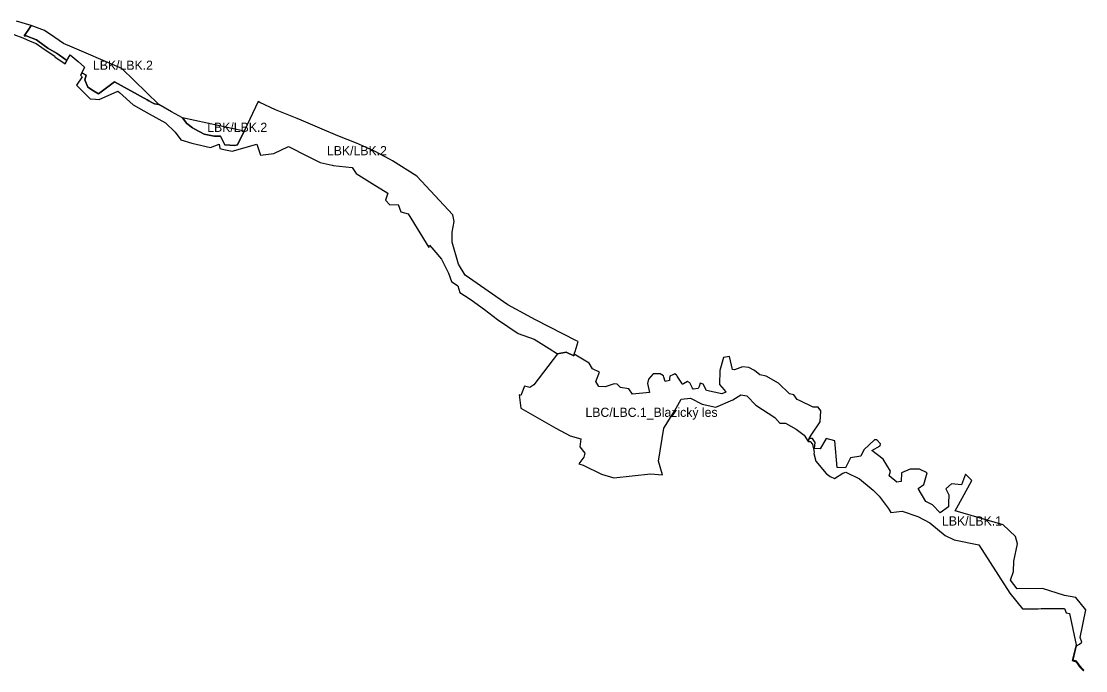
# Model space of a CAD drawing. Extents: x -521980 to -518833, y -1141793 to -1140093.
# Drawn here: x -520226 to -518833, y -1141674 to -1140823 of the extents above; entities that cross this region are included whole.
import ezdxf

# ---------------------------------------------------------------- set-up
doc = ezdxf.new("R2010")
doc.units = 0
for name, color, linetype in [('91270013', 7, 'Continuous'), ('91280013', 7, 'Continuous'), ('91280023', 7, 'Continuous')]:
    doc.layers.add(name, color=color, linetype=linetype)

msp = doc.modelspace()

# ---------------------------------------------------------------- linework, layer by layer
at = {"layer": '91270013'}
msp.add_lwpolyline([(-519524.47, -1141258.63), (-519555.19, -1141299.24), (-519560.68, -1141302.79), (-519567.64, -1141300.94), (-519572.4, -1141313.2), (-519574.58, -1141312.28), (-519572.25, -1141330.06), (-519526.67, -1141356.01), (-519507.9, -1141366.28), (-519493.9, -1141370.24), (-519494.92, -1141380.6), (-519488.36, -1141388.76), (-519489.99, -1141393.96), (-519496.45, -1141402.69), (-519490.7, -1141404.57), (-519466.91, -1141416.21), (-519450.75, -1141420.94), (-519402.53, -1141416.1), (-519386.73, -1141417.35), (-519392.16, -1141399.31), (-519385.2, -1141356.16), (-519371.28, -1141333.68), (-519362.63, -1141317.99), (-519350.02, -1141316.82), (-519334.98, -1141324.76), (-519317.19, -1141328.69), (-519294.89, -1141319.05), (-519284.21, -1141312.41), (-519276.42, -1141313.78), (-519264.89, -1141325.79), (-519239.84, -1141342.13), (-519233.32, -1141349.64), (-519225.95, -1141349.55), (-519211.68, -1141357.48), (-519201.22, -1141365.24), (-519195.98, -1141373.38), (-519194.96, -1141369.43), (-519192.3, -1141365.49), (-519180.48, -1141347.87), (-519179.55, -1141333.52), (-519183.26, -1141328.59), (-519189.49, -1141328.56), (-519206.65, -1141320.44), (-519210.53, -1141318.6), (-519214.82, -1141312.52), (-519220.59, -1141311.22), (-519234.97, -1141297.23), (-519251.16, -1141288.07), (-519259.58, -1141286.33), (-519266.36, -1141280.43), (-519273.89, -1141276.5), (-519282.24, -1141275.71), (-519292.59, -1141279.53), (-519295.1, -1141279.15), (-519299.19, -1141262.23), (-519306.82, -1141263.47), (-519311.83, -1141280.54), (-519312.28, -1141299.01), (-519305.93, -1141305.82), (-519304.74, -1141307.68), (-519303.86, -1141309.05), (-519309.3, -1141311.02), (-519329.18, -1141306.68), (-519333.7, -1141298.67), (-519337.51, -1141297.26), (-519339.07, -1141301.4), (-519340.12, -1141304.19), (-519346.7, -1141305.23), (-519347.55, -1141303.63), (-519351.06, -1141296.96), (-519353.95, -1141294.93), (-519359.18, -1141298.18), (-519360.6, -1141299.07), (-519361.74, -1141297.24), (-519367.51, -1141288.01), (-519368.04, -1141287.17), (-519370.55, -1141284.76), (-519373.33, -1141286.11), (-519377.33, -1141288.06), (-519377.66, -1141291.53), (-519377.88, -1141293.85), (-519383.31, -1141295.11), (-519385.12, -1141289.38), (-519385.69, -1141287.55), (-519389.78, -1141285.13), (-519399.13, -1141285.07), (-519405.2, -1141292.02), (-519406.68, -1141297.5), (-519403.83, -1141309.49), (-519426.16, -1141311.48), (-519430.99, -1141304.77), (-519441.7, -1141302.87), (-519446.22, -1141298.48), (-519449.98, -1141298.09), (-519461.74, -1141302), (-519470.14, -1141301.74), (-519474.2, -1141295.1), (-519469.18, -1141282.65), (-519478.58, -1141278.28), (-519482.78, -1141270.88), (-519502.46, -1141259.44), (-519502.94, -1141261.24), (-519512.96, -1141256.69), (-519524.47, -1141258.63)], dxfattribs=at)
at = {"layer": '91280013'}
for points in [[(-520166.62, -1140874.78), (-520176.48, -1140867.88), (-520180.27, -1140865.22), (-520191.59, -1140858.73), (-520196.46, -1140855.08), (-520206.43, -1140847.59), (-520220.12, -1140842.45), (-520222.55, -1140842.43), (-520217.49, -1140834.9), (-520213.5, -1140828.96), (-520232.81, -1140823.41)], [(-520236.26, -1140840.92), (-520224.47, -1140845.06), (-520214.8, -1140849.22), (-520206.95, -1140852.59), (-520199.46, -1140857.65), (-520181.95, -1140869.32), (-520182.55, -1140869.96), (-520168.95, -1140879.03), (-520167.79, -1140876.9), (-520166.62, -1140874.78)], [(-519524.47, -1141258.63), (-519512.96, -1141256.69), (-519502.94, -1141261.24), (-519502.46, -1141259.44), (-519501.64, -1141256.67), (-519501.33, -1141255.67), (-519497.33, -1141242.73), (-519499.59, -1141241.58), (-519553.27, -1141214.2), (-519589.6, -1141194.6), (-519645.14, -1141155.67), (-519653.82, -1141141.35), (-519662.06, -1141112.71), (-519662.35, -1141099.54), (-519660.92, -1141092.62), (-519659.49, -1141085.69), (-519661.22, -1141076.98), (-519702.3, -1141032.7), (-519708.41, -1141026.12), (-519740.29, -1141006.03), (-519743.47, -1141004.35), (-519764.04, -1140993.49), (-519787.36, -1140982.97), (-519811.83, -1140973.18), (-519832.3, -1140964.53), (-519841.67, -1140960.58), (-519859.94, -1140952.86), (-519865.12, -1140950.76), (-519893.61, -1140939.25), (-519914.16, -1140929.63), (-519916.21, -1140928.63), (-519934.8, -1140967.08), (-519943.51, -1140985.08), (-519947.03, -1140986.05), (-519959.93, -1140985.31), (-519965.47, -1140973.69), (-519974.08, -1140974.02), (-519986.94, -1140971.3), (-519999.3, -1140964.63), (-520002.28, -1140962.91), (-520009.84, -1140957.29), (-520015.17, -1140949.95), (-520029.76, -1140941.98), (-520046.33, -1140932.29), (-520051.93, -1140931.48), (-520055.67, -1140929.56), (-520059.41, -1140927.64), (-520061.67, -1140926.36), (-520104.55, -1140902.75), (-520125.39, -1140918.45), (-520131.65, -1140914.52), (-520139.09, -1140909.85), (-520143.26, -1140900.05), (-520141.61, -1140894.1), (-520147.23, -1140890.72), (-520148.27, -1140892.97), (-520148.74, -1140894), (-520146.75, -1140896.12), (-520154.18, -1140907.23), (-520136.24, -1140924.81), (-520129.31, -1140925.55), (-520124.49, -1140925.8), (-520100.12, -1140914.78), (-520097.88, -1140916.76), (-520079.83, -1140932.73), (-520058.84, -1140944.58), (-520037.81, -1140956.24), (-520025.01, -1140968.52), (-520017.73, -1140978.78), (-520003.11, -1140982.94), (-519978.85, -1140988.86), (-519967.54, -1140984.38), (-519966.67, -1140989.91), (-519961.08, -1140991.39), (-519950.36, -1140993.42), (-519918.04, -1140984.12), (-519913.39, -1140998.68), (-519895.77, -1140996.31), (-519876.6, -1140987.29), (-519851.59, -1141000.07), (-519835.08, -1141008.27), (-519819.26, -1141011.99), (-519818.09, -1141012.26), (-519793.36, -1141014.98), (-519787.79, -1141022.58), (-519766.87, -1141035.85), (-519746.51, -1141048.43), (-519749.67, -1141057.47), (-519744.08, -1141063.56), (-519732.93, -1141063.24), (-519729.51, -1141072.8), (-519719.95, -1141075.61), (-519692.8, -1141119.72), (-519691.83, -1141116.63), (-519686.19, -1141123.12), (-519676.06, -1141134.77), (-519667.13, -1141153.28), (-519663.19, -1141164.28), (-519654.81, -1141169.94), (-519652.19, -1141178.57), (-519646.01, -1141182.51), (-519637.37, -1141188.02), (-519620.04, -1141200.94), (-519602.71, -1141213.86), (-519575.99, -1141232.08), (-519554.92, -1141239.55), (-519545.8, -1141245.26), (-519535.14, -1141251.95), (-519524.47, -1141258.63)], [(-519195.98, -1141373.38), (-519193.48, -1141373.59), (-519190.53, -1141377.07), (-519188.19, -1141387.74), (-519188.81, -1141389.21), (-519185.95, -1141399.11), (-519172.73, -1141415.6), (-519167.27, -1141419.59), (-519161.79, -1141421.83), (-519150.96, -1141415.24), (-519146.88, -1141413.75), (-519128.84, -1141422.33), (-519113.73, -1141434.94), (-519111.28, -1141437.32), (-519103.24, -1141445.12), (-519091.6, -1141460.78), (-519089.22, -1141464.23), (-519087.76, -1141466.33), (-519073.04, -1141464.69), (-519052.51, -1141471.71), (-519036.96, -1141480), (-519016.8, -1141496.81), (-519004.9, -1141502.52), (-518972.83, -1141508.64), (-518931.99, -1141572.05), (-518915.44, -1141592.52), (-518895.23, -1141592.43), (-518891.05, -1141592.41), (-518886.88, -1141592.39), (-518870.9, -1141592.32), (-518860.72, -1141592.27), (-518858.42, -1141598.04), (-518853.84, -1141598.54), (-518845.18, -1141639.97), (-518850.48, -1141660.34), (-518845.32, -1141661.82), (-518840.87, -1141668.48), (-518835.69, -1141673.66), (-518835.18, -1141672.79), (-518835.83, -1141672.48), (-518837.05, -1141671.02), (-518840.16, -1141667.91), (-518844.75, -1141661.05), (-518849.41, -1141659.71), (-518844.96, -1141640.98), (-518840.9, -1141638.87), (-518837.74, -1141636.08), (-518840.17, -1141630.23), (-518832.78, -1141593.74), (-518845.76, -1141577.71), (-518860.53, -1141575.36), (-518889.18, -1141566.18), (-518922.51, -1141566.63), (-518931.43, -1141555), (-518927.11, -1141543.74), (-518927.02, -1141530.23), (-518922.06, -1141507.35), (-518924.49, -1141497.8), (-518940.71, -1141482.48), (-519003.59, -1141464.2), (-519001.41, -1141460.26), (-518994.55, -1141447.83), (-518981.74, -1141424.63), (-518989.97, -1141416.33), (-518995.53, -1141430.25), (-519008.63, -1141428.83), (-519015.74, -1141435.38), (-519011.87, -1141443.33), (-519012.34, -1141454.52), (-519012.53, -1141459.04), (-519023.29, -1141466.86), (-519033.46, -1141456.53), (-519042.3, -1141452.19), (-519052, -1141435.32), (-519044.82, -1141429.69), (-519040.39, -1141414.74), (-519050.33, -1141409.98), (-519062.78, -1141409.81), (-519073.85, -1141414.66), (-519074.35, -1141425.83), (-519080.26, -1141427.02), (-519090.32, -1141418.48), (-519088.18, -1141412.32), (-519098.12, -1141396.65), (-519112.59, -1141385.36), (-519101.7, -1141379.43), (-519101.55, -1141376.47), (-519106.36, -1141371.37), (-519109.18, -1141371.2), (-519123.4, -1141384.39), (-519127.25, -1141392.73), (-519140.85, -1141394.82), (-519147.23, -1141408.12), (-519158.19, -1141407.51), (-519161.16, -1141372.68), (-519172.49, -1141369.75), (-519180.54, -1141383.29), (-519188.01, -1141382.78), (-519187.2, -1141374.82), (-519190.42, -1141369.81), (-519194.96, -1141369.43), (-519195.98, -1141373.38)]]:
    msp.add_lwpolyline(points, dxfattribs=at)
at = {"layer": '91280023'}
for points in [[(-520147.23, -1140890.72), (-520141.61, -1140894.1), (-520143.26, -1140900.05), (-520139.09, -1140909.85), (-520131.65, -1140914.52), (-520125.39, -1140918.45), (-520104.55, -1140902.75), (-520061.67, -1140926.36), (-520059.41, -1140927.64), (-520055.67, -1140929.56), (-520051.93, -1140931.48), (-520046.33, -1140932.29), (-520094.9, -1140885.23), (-520122.13, -1140873.55), (-520138.6, -1140866.49), (-520159.88, -1140857.36), (-520170.98, -1140852.6), (-520182.58, -1140844.72), (-520196.23, -1140835.45), (-520213.5, -1140828.96), (-520217.49, -1140834.9), (-520222.55, -1140842.43), (-520220.12, -1140842.45), (-520206.43, -1140847.59), (-520196.46, -1140855.08), (-520191.59, -1140858.73), (-520180.27, -1140865.22), (-520176.48, -1140867.88), (-520166.62, -1140874.78), (-520162.5, -1140867.24), (-520152.09, -1140876.15), (-520143.83, -1140883.35), (-520147.23, -1140890.72)], [(-519934.8, -1140967.08), (-520015.17, -1140949.95), (-520009.84, -1140957.29), (-520002.28, -1140962.91), (-519999.3, -1140964.63), (-519986.94, -1140971.3), (-519974.08, -1140974.02), (-519965.47, -1140973.69), (-519959.93, -1140985.31), (-519947.03, -1140986.05), (-519943.51, -1140985.08), (-519934.8, -1140967.08)]]:
    msp.add_lwpolyline(points, dxfattribs=at)

# ---------------------------------------------------------------- texts
at = {"layer": '91270013'}
msp.add_text('LBC/LBC.1_Blazický les', height=12, rotation=0, dxfattribs=at).set_placement((-519487.77, -1141341.34))
at = {"layer": '91280013'}
for s, rotation, p in [('LBK/LBK.2', 0, (-519826.22, -1140998.77)), ('LBK/LBK.1', 360, (-519020.93, -1141483.62))]:
    msp.add_text(s, height=12, rotation=rotation, dxfattribs=at).set_placement(p)
at = {"layer": '91280023'}
for p in [(-520132.6, -1140886.93), (-519982.99, -1140968.19)]:
    msp.add_text('LBK/LBK.2', height=12, rotation=360, dxfattribs=at).set_placement(p)

doc.saveas('drawing.dxf')
